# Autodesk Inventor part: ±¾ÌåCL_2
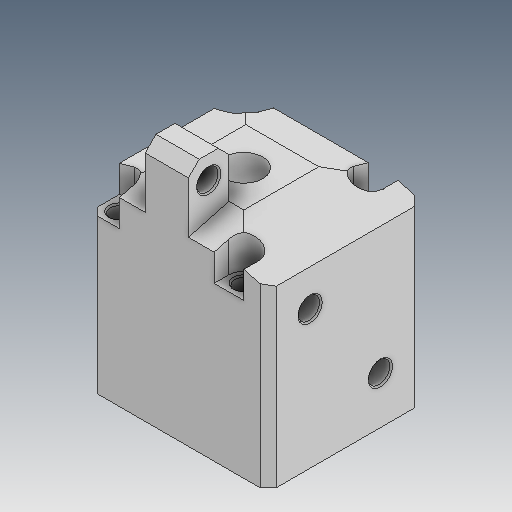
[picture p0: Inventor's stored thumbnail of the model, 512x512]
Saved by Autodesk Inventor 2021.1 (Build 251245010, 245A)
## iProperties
Created: 2019-04
Part Number: ±¾ÌåCL_2
Material: Ogólny
Document SubType Name: Modeling
Designer: user
Density: 1 g/cm^3
Appearance: Domyślna
Author: user
Revision Number: ÈÎºÎ
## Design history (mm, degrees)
feature "ÊäÈë1"
node "Bryła1"
